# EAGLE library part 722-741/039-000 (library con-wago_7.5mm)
Serie 722, Federleiste mit Verriegelungsklinken / Series 722, Female connector with locking levers Polzahl / Pole No.: 11 Bemessungsspannung / Rated Voltage: 400 V Nennstrom / Nominal Current: 12 A Farbe / Color: xxxx / xxxx Stand: 01.01.2012. Die jeweils aktuellen Daten zu diesem Artikel finden Sie in unserem Produktkatalog, den Sie unter www.wago.com einsehen können. As of: 01/01/2012. Please find the newest data for this article in our product catalogue, which can be viewed under www.wago.com.
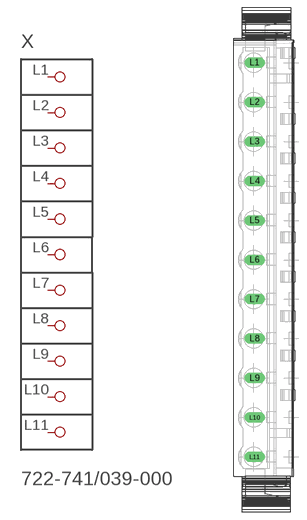
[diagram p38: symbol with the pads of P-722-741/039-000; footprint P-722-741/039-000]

Designator prefix X

## 722-741/039-000  [P-722-741/039-000]
L1  P1
L2  P2
L3  P3
L4  P4
L5  P5
L6  P6
L7  P7
L8  P8
L9  P9
L10  P10
L11  P11

## Footprint P-722-741/039-000 (pad centres in mm)
drill 1.3 long: L1 -2.233,37.5; L2 -2.233,30; L3 -2.233,22.5; L4 -2.233,15; L5 -2.233,7.5; L6 -2.233,0; L7 -2.233,-7.5; L8 -2.233,-15; L9 -2.233,-22.5; L10 -2.233,-30; L11 -2.233,-37.5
